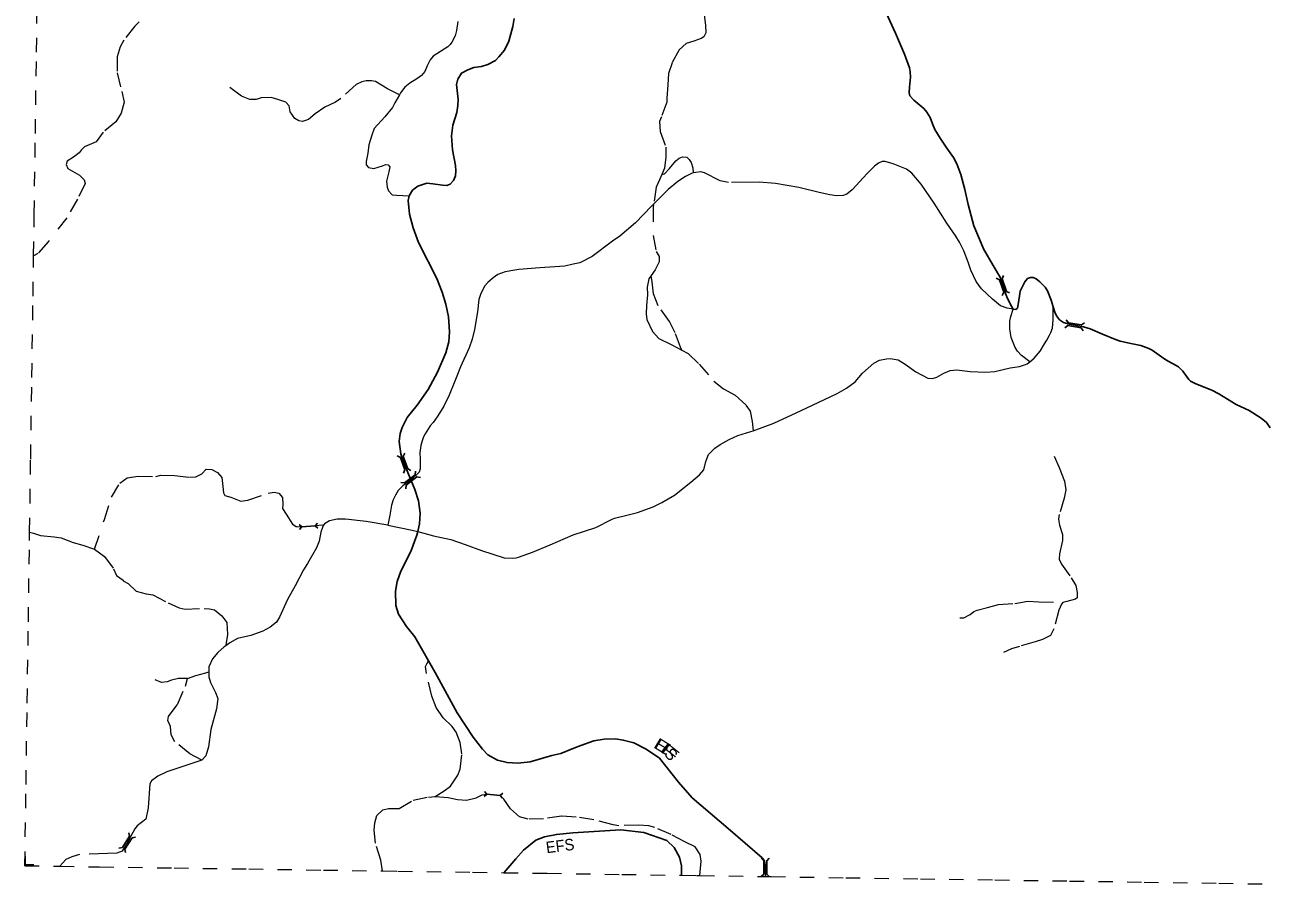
# Model space of a CAD drawing. Extents: x 703.1 to 728.9, y 7316.2 to 7344.3.
# Drawn here: x 703.06 to 711.69, y 7316.45 to 7322.44 of the extents above; entities that cross this region are included whole.
import ezdxf
from ezdxf.enums import TextEntityAlignment as Align

# ---------------------------------------------------------------- set-up
doc = ezdxf.new("R2010")
doc.units = 0
doc.header["$LTSCALE"] = 0.032
for name, pattern in [('DOTTED', [1.5, 0.3, -1.2]), ('LONG_DASHED', [7.5, 6, -1.5]), ('MEDIUM_DASHED', [4.5, 3, -1.5]), ('SHORT_DASHED', [2.7, 1.5, -1.2])]:
    doc.linetypes.add(name, pattern=pattern)
for name, color, linetype, lineweight in [('10', 7, 'Continuous', 25), ('15', 7, 'Continuous', 25), ('31', 7, 'Continuous', 25), ('4', 7, 'LONG_DASHED', 25), ('5', 7, 'LONG_DASHED', 13), ('58', 7, 'SHORT_DASHED', 13), ('6', 7, 'MEDIUM_DASHED', 13), ('63', 7, 'Continuous', 25), ('7', 7, 'DOTTED', 13)]:
    doc.layers.add(name, color=color, linetype=linetype, lineweight=lineweight)
doc.layers.add('61', color=7, linetype='Continuous')

msp = doc.modelspace()

# ---------------------------------------------------------------- linework, layer by layer
at = {"layer": '10'}
for p, q in [((709.8594, 7320.7025), (709.8485, 7320.68)), ((709.8787, 7320.5926), (709.8485, 7320.68)), ((709.8598, 7320.5861), (709.8487, 7320.5637)), ((709.901, 7320.5818), (709.8787, 7320.5926)), ((710.294, 7320.3948), (710.3086, 7320.3746)), ((710.3999, 7320.3595), (710.3086, 7320.3746)), ((710.42, 7320.374), (710.3999, 7320.3595)), ((710.3966, 7320.3397), (710.411, 7320.3194)), ((705.7005, 7319.469), (705.6899, 7319.4464)), ((705.7213, 7319.3594), (705.6899, 7319.4464)), ((705.7025, 7319.3526), (705.6918, 7319.3301)), ((705.7438, 7319.3489), (705.7213, 7319.3594)), ((705.776, 7319.3438), (705.7728, 7319.3191)), ((705.6748, 7319.2658), (705.6996, 7319.2627)), ((705.7728, 7319.3191), (705.6996, 7319.2627)), ((705.785, 7319.3033), (705.8097, 7319.2999)), ((703.7854, 7316.8316), (703.7906, 7316.8074)), ((703.7906, 7316.8074), (703.7402, 7316.7299)), ((703.8074, 7316.7965), (703.8318, 7316.8015)), ((703.7158, 7316.7246), (703.7402, 7316.7299)), ((708.232, 7316.655), (708.2144, 7316.6373)), ((708.2144, 7316.5448), (708.2144, 7316.6373)), ((708.1944, 7316.5448), (708.1767, 7316.5273)), ((708.232, 7316.5273), (708.2144, 7316.5448))]:
    msp.add_line(p, q, dxfattribs=at)
for points in [[(709.8598, 7320.5861), (709.8296, 7320.6735), (709.8071, 7320.6845)], [(710.3966, 7320.3397), (710.3053, 7320.3548), (710.285, 7320.3403)], [(705.7025, 7319.3526), (705.6711, 7319.4396), (705.6485, 7319.4502)], [(705.785, 7319.3033), (705.7118, 7319.2468), (705.7086, 7319.222)], [(703.8074, 7316.7965), (703.7569, 7316.7189), (703.7621, 7316.6945)], [(708.1944, 7316.5448), (708.1944, 7316.6373), (708.1767, 7316.655)]]:
    msp.add_lwpolyline(points, dxfattribs=at)
at = {"layer": '15'}
for points in [[(706.4601, 7322.4886), (706.4525, 7322.4332), (706.4236, 7322.3299), (706.3933, 7322.2682), (706.3537, 7322.2223), (706.331, 7322.1958), (706.2769, 7322.1694), (706.2328, 7322.1555), (706.1812, 7322.148), (706.1384, 7322.1316), (706.0956, 7322.1089), (706.0704, 7322.0661), (706.0604, 7322.0296), (706.073, 7321.925), (706.0698, 7321.8841), (706.0622, 7321.8363), (706.0346, 7321.7481), (706.0257, 7321.6725), (706.0314, 7321.5749), (706.0528, 7321.4679), (706.0566, 7321.4301), (706.0541, 7321.3948), (706.039, 7321.3621), (706.0163, 7321.3369), (705.9924, 7321.3293), (705.9622, 7321.3306), (705.8955, 7321.3407), (705.8533, 7321.3438), (705.7916, 7321.3236), (705.7551, 7321.2947), (705.7314, 7321.2569)], [(705.7314, 7321.2569), (705.7236, 7321.2241), (705.7349, 7321.1284), (705.7589, 7321.034), (705.7972, 7320.9313), (705.9244, 7320.6832), (705.9602, 7320.5881)], [(705.9602, 7320.5881), (705.9867, 7320.5049), (706.0055, 7320.4168), (706.0106, 7320.3122), (706.0061, 7320.2411), (705.9873, 7320.1655), (705.9281, 7320.0308), (705.8632, 7319.9117), (705.7864, 7319.8034), (705.7172, 7319.7165), (705.6825, 7319.6479), (705.6687, 7319.6063), (705.6624, 7319.5497), (705.6737, 7319.4653), (705.697, 7319.3979), (705.7436, 7319.2842)], [(705.7436, 7319.2842), (705.7713, 7319.2165), (705.7959, 7319.1366), (705.8085, 7319.0522), (705.8035, 7318.9791), (705.7913, 7318.9244)], [(705.7913, 7318.9244), (705.7858, 7318.8998), (705.7424, 7318.7858), (705.6744, 7318.6497), (705.6493, 7318.578), (705.6373, 7318.5093), (705.6385, 7318.4098), (705.6587, 7318.3506), (705.7128, 7318.2637), (705.7714, 7318.1938), (705.8268, 7318.0956), (705.8658, 7318.0262), (705.9111, 7317.9457)], [(705.9111, 7317.9457), (706.064, 7317.6643), (706.1755, 7317.4949), (706.2409, 7317.4117), (706.2774, 7317.3727), (706.3442, 7317.3362), (706.4121, 7317.3198), (706.4864, 7317.316), (706.572, 7317.3248), (706.7212, 7317.3696), (706.7842, 7317.3822), (706.8761, 7317.4199), (706.9239, 7317.4376), (707.0146, 7317.4703), (707.0863, 7317.4829), (707.165, 7317.4836), (707.2179, 7317.476), (707.2922, 7317.4571), (707.3765, 7317.4118), (707.4697, 7317.3513), (707.6006, 7317.1826), (707.6957, 7317.0749), (707.9475, 7316.8608), (708.1822, 7316.6586), (708.198, 7316.6379), (708.2043, 7316.6102), (708.2052, 7316.5481), (708.2055, 7316.5281)], [(706.388, 7316.5546), (706.4717, 7316.6498), (706.5265, 7316.7112), (706.6104, 7316.7805), (706.6717, 7316.8048), (706.7539, 7316.8209), (706.8685, 7316.8322), (707.2007, 7316.8532), (707.362, 7316.8338), (707.5201, 7316.7773), (707.5717, 7316.7289), (707.6088, 7316.6627), (707.6217, 7316.603), (707.6217, 7316.5366)]]:
    msp.add_lwpolyline(points, dxfattribs=at)
at = {"layer": '31'}
for p, q in [((704.967, 7318.9734), (704.9858, 7318.957)), ((704.9858, 7318.957), (704.9694, 7318.9382)), ((705.0781, 7318.9632), (704.9858, 7318.957)), ((705.0944, 7318.9819), (705.0781, 7318.9632)), ((705.0781, 7318.9632), (705.0968, 7318.9467)), ((706.2718, 7317.0995), (706.2525, 7317.0836)), ((706.2558, 7317.1187), (706.2718, 7317.0995)), ((706.3639, 7317.0907), (706.2718, 7317.0995)), ((706.383, 7317.1065), (706.3639, 7317.0907)), ((706.3639, 7317.0907), (706.3796, 7317.0714))]:
    msp.add_line(p, q, dxfattribs=at)
at = {"layer": '4'}
for points in [[(709.0442, 7322.5275), (709.1086, 7322.386), (709.1711, 7322.2413), (709.2064, 7322.1454), (709.2114, 7322.1169), (709.2133, 7322.0807), (709.2061, 7322.011), (709.2029, 7321.9716), (709.2086, 7321.95), (709.2362, 7321.9202), (709.3047, 7321.8631), (709.3257, 7321.8377), (709.3491, 7321.8003), (709.3663, 7321.7559), (709.3805, 7321.7178), (709.4186, 7321.6569), (709.4655, 7321.5871), (709.5109, 7321.5223), (709.5337, 7321.4792), (709.5619, 7321.4036), (709.5905, 7321.3008), (709.613, 7321.1968), (709.6424, 7321.0832), (709.6526, 7321.0476), (709.6922, 7320.955), (709.7201, 7320.889), (709.7871, 7320.7723), (709.8375, 7320.6867), (709.847, 7320.6619), (709.8628, 7320.601), (709.8866, 7320.5433), (709.9158, 7320.4856), (709.9266, 7320.4691)], [(709.9266, 7320.4691), (709.945, 7320.4672), (709.9564, 7320.4767), (709.9608, 7320.5021), (709.9685, 7320.5623), (709.9742, 7320.5953), (710.0071, 7320.6588), (710.0243, 7320.6823), (710.0452, 7320.6899), (710.0649, 7320.6899), (710.0858, 7320.6797), (710.1112, 7320.6601), (710.1476, 7320.6213), (710.1647, 7320.596), (710.1888, 7320.5325), (710.2038, 7320.4856)], [(710.2038, 7320.4856), (710.2152, 7320.4494), (710.2272, 7320.4221), (710.2475, 7320.3961)], [(710.2475, 7320.3961), (710.2754, 7320.3771), (710.316, 7320.3638), (710.414, 7320.3466), (710.4597, 7320.3333), (710.5453, 7320.2959), (710.637, 7320.259)], [(710.637, 7320.259), (710.6687, 7320.247), (710.7436, 7320.2305), (710.8121, 7320.2172), (710.8669, 7320.1968), (710.891, 7320.1848), (710.9563, 7320.1378), (710.9862, 7320.1169), (711.0731, 7320.0687), (711.1032, 7320.0395), (711.145, 7319.9811), (711.1571, 7319.9684), (711.1945, 7319.9494), (711.3042, 7319.9056), (711.3534, 7319.8802), (711.4746, 7319.8059), (711.5634, 7319.7647), (711.6474, 7319.7114), (711.6835, 7319.6815), (711.7089, 7319.6454)]]:
    msp.add_lwpolyline(points, dxfattribs=at)
at = {"layer": '5'}
for points in [[(706.0685, 7322.4684), (706.0604, 7322.4044), (706.0508, 7322.3676), (706.0288, 7322.3242), (706.017, 7322.308), (706.0012, 7322.2911), (705.8983, 7322.2257), (705.8784, 7322.2006), (705.8571, 7322.1587), (705.8398, 7322.1198), (705.8178, 7322.0925), (705.7847, 7322.0683), (705.7369, 7322.0388), (705.7023, 7322.0109), (705.6722, 7321.9726), (705.6641, 7321.9587)], [(705.6641, 7321.9587), (705.6314, 7321.9028), (705.616, 7321.8697), (705.563, 7321.8057), (705.4884, 7321.724), (705.4715, 7321.6784), (705.4509, 7321.6107), (705.4447, 7321.5534), (705.4322, 7321.4945), (705.4322, 7321.4725), (705.4483, 7321.4526), (705.4873, 7321.446), (705.5468, 7321.4658), (705.5682, 7321.4747), (705.5866, 7321.471), (705.5968, 7321.4577), (705.5914, 7321.4224), (705.5737, 7321.3584), (705.5796, 7321.3158), (705.5884, 7321.2922), (705.6141, 7321.2635), (705.6443, 7321.2606), (705.7314, 7321.2569)], [(709.9266, 7320.4691), (709.8848, 7320.4758), (709.8379, 7320.4934), (709.7816, 7320.5394), (709.7053, 7320.6104), (709.6676, 7320.6608), (709.6307, 7320.7401), (709.6121, 7320.7945), (709.583, 7320.8733), (709.5522, 7320.9339), (709.5285, 7320.976), (709.4639, 7321.0671), (709.3761, 7321.2065), (709.2858, 7321.3363), (709.2224, 7321.4146), (709.1838, 7321.4405), (709.0933, 7321.4792), (709.0363, 7321.4948), (709.0162, 7321.4948), (708.9893, 7321.484), (708.9619, 7321.4615), (708.912, 7321.4106), (708.808, 7321.2986), (708.7696, 7321.2687), (708.7451, 7321.2594), (708.6977, 7321.2569), (708.6517, 7321.2623), (708.5786, 7321.2805), (708.4367, 7321.3142), (708.275, 7321.3417), (708.1612, 7321.3514), (707.9482, 7321.348), (707.8921, 7321.3617), (707.783, 7321.4155), (707.7576, 7321.4229), (707.7228, 7321.4195), (707.7029, 7321.4152)], [(707.7029, 7321.4152), (707.691, 7321.4126), (707.6504, 7321.3916), (707.5966, 7321.3548), (707.5296, 7321.3005), (707.429, 7321.1982)], [(707.429, 7321.1982), (707.4146, 7321.1835), (707.3028, 7321.0699), (707.1944, 7320.9773), (707.1426, 7320.9426), (707.0014, 7320.8344), (706.9175, 7320.7903), (706.8705, 7320.781), (706.8123, 7320.7683), (706.6388, 7320.7565), (706.4937, 7320.7453), (706.4658, 7320.7409), (706.398, 7320.7281), (706.3481, 7320.71), (706.3149, 7320.6865), (706.2784, 7320.6552), (706.2559, 7320.6288), (706.2408, 7320.5994), (706.23, 7320.5779), (706.2165, 7320.5353), (706.2053, 7320.4496), (706.186, 7320.3288), (706.1686, 7320.2597), (706.1491, 7320.201), (706.0892, 7320.0678), (706.0664, 7320.015), (706.0498, 7319.9695), (706.0085, 7319.872), (705.9713, 7319.7957), (705.9312, 7319.7291), (705.8975, 7319.6826), (705.8767, 7319.6581), (705.8429, 7319.6028), (705.8317, 7319.5817), (705.8224, 7319.5538), (705.8124, 7319.522), (705.805, 7319.4736), (705.807, 7319.4261), (705.8082, 7319.359), (705.8019, 7319.336), (705.7493, 7319.2885), (705.7436, 7319.2842)], [(710.0405, 7320.1035), (709.9827, 7320.148), (709.9553, 7320.1784), (709.9392, 7320.2028), (709.9111, 7320.2714), (709.9013, 7320.3321), (709.903, 7320.3864), (709.9084, 7320.4192), (709.9266, 7320.4691)], [(710.0405, 7320.1035), (710.0711, 7320.1285), (710.1136, 7320.1779), (710.144, 7320.2284), (710.1599, 7320.2533), (710.1785, 7320.2886), (710.1878, 7320.3081), (710.1986, 7320.3375), (710.2028, 7320.3948), (710.2038, 7320.4856)], [(708.1199, 7319.6242), (708.2648, 7319.6762), (708.4177, 7319.7501), (708.5327, 7319.802), (708.7042, 7319.8822), (708.7671, 7319.9209), (708.8273, 7319.964), (708.8786, 7320.0257), (708.9571, 7320.0937), (708.9975, 7320.1143), (709.0465, 7320.1246), (709.0724, 7320.1275), (709.1262, 7320.1167), (709.1761, 7320.0874), (709.25, 7320.0345), (709.3339, 7319.9904), (709.3662, 7319.9884), (709.3961, 7319.9963), (709.4433, 7320.0241), (709.4707, 7320.0369), (709.4869, 7320.0427), (709.5338, 7320.0467), (709.6265, 7320.0369), (709.7347, 7320.0325), (709.7976, 7320.0364), (709.9037, 7320.0623), (709.9705, 7320.0697), (710.0052, 7320.0814), (710.0238, 7320.0888), (710.0405, 7320.1035)], [(705.7913, 7318.9244), (705.9012, 7318.8939), (706.0199, 7318.869), (706.1209, 7318.8342), (706.234, 7318.7926), (706.3923, 7318.7426), (706.4508, 7318.7397), (706.4738, 7318.7412), (706.4914, 7318.7461), (706.5873, 7318.7818), (706.7104, 7318.8332), (706.8711, 7318.9018), (707.0269, 7318.9527), (707.1367, 7319.0089), (707.1573, 7319.0182), (707.2434, 7319.0373), (707.3165, 7319.0574), (707.4257, 7319.0966), (707.4861, 7319.1254), (707.5732, 7319.1768), (707.687, 7319.2674), (707.7484, 7319.3188), (707.7768, 7319.3521), (707.7924, 7319.4118), (707.8112, 7319.4593), (707.8548, 7319.5044), (707.892, 7319.5283), (707.9539, 7319.5646), (708.0131, 7319.591), (708.1036, 7319.6184), (708.1199, 7319.6242)], [(705.7436, 7319.2842), (705.6866, 7319.2415), (705.6543, 7319.2092), (705.6358, 7319.1779), (705.6214, 7319.1436), (705.6082, 7319.1083), (705.5964, 7319.0374), (705.5844, 7318.9678)], [(705.5844, 7318.9678), (705.4339, 7318.9951), (705.2899, 7319.0096), (705.2318, 7319.0096), (705.1796, 7318.9989), (705.1429, 7318.9777), (705.1371, 7318.968)], [(705.1371, 7318.968), (705.1313, 7318.9583), (705.1178, 7318.9206), (705.1071, 7318.8587), (705.0888, 7318.8103), (705.0255, 7318.703), (704.9974, 7318.6594), (704.9394, 7318.5472), (704.8877, 7318.4534), (704.8316, 7318.3306), (704.8098, 7318.2938), (704.7668, 7318.259), (704.7146, 7318.2329), (704.6325, 7318.2019), (704.5387, 7318.1806), (704.4865, 7318.1506), (704.4582, 7318.1308)], [(705.5844, 7318.9678), (705.7527, 7318.9351), (705.7913, 7318.9244)], [(704.4582, 7318.1308), (704.4478, 7318.1236), (704.4033, 7318.0839), (704.3651, 7318.0403), (704.3409, 7317.9842), (704.3405, 7317.9494)], [(704.3405, 7317.9494), (704.34, 7317.9146), (704.3525, 7317.8759), (704.3868, 7317.8052), (704.4033, 7317.7636), (704.3936, 7317.692), (704.3554, 7317.5489), (704.338, 7317.4289), (704.3201, 7317.367), (704.2911, 7317.3361)], [(704.2911, 7317.3361), (704.1316, 7317.2819), (704.0499, 7317.2549), (703.9861, 7317.2249), (703.9435, 7317.193), (703.931, 7317.1726), (703.9203, 7317.0053), (703.9043, 7316.9269), (703.8434, 7316.8805), (703.826, 7316.8582), (703.768, 7316.7528), (703.7385, 7316.7053), (703.7027, 7316.6899), (703.4436, 7316.6802), (703.3895, 7316.6657), (703.3484, 7316.6453), (703.3054, 7316.5992)]]:
    msp.add_lwpolyline(points, dxfattribs=at)
at = {"layer": '58'}
msp.add_line((703.0632, 7316.6027), (703.3054, 7316.5992), dxfattribs=at)
for points in [[(703.1239, 7320.8393), (703.128, 7321.1237), (703.1361, 7321.6888), (703.1442, 7322.254), (703.1522, 7322.8191), (703.1603, 7323.3842), (703.1684, 7323.9493), (703.1684, 7323.9498)], [(703.0964, 7318.9203), (703.1037, 7319.4283), (703.1118, 7319.9935), (703.1199, 7320.5586), (703.1239, 7320.8393)], [(703.0632, 7316.6027), (703.0713, 7317.1678), (703.0794, 7317.733), (703.0875, 7318.2981), (703.0956, 7318.8632), (703.0964, 7318.9203)], [(703.3054, 7316.5992), (703.5813, 7316.5953), (704.0995, 7316.5878), (704.6177, 7316.5803), (705.1358, 7316.5728), (705.547, 7316.5668)], [(705.547, 7316.5668), (705.654, 7316.5653), (706.1722, 7316.5578), (706.388, 7316.5546)], [(706.388, 7316.5546), (706.6903, 7316.5502), (707.2085, 7316.5427), (707.6217, 7316.5366)], [(707.6217, 7316.5366), (707.7267, 7316.5351), (707.7507, 7316.5347), (708.2055, 7316.5281)], [(708.2055, 7316.5281), (708.2448, 7316.5275), (708.763, 7316.5198), (709.2812, 7316.5122), (709.7993, 7316.5045), (710.3175, 7316.4968), (710.8357, 7316.4891), (711.3539, 7316.4814), (711.872, 7316.4736), (712.3902, 7316.4659), (712.9084, 7316.4581), (713.1751, 7316.4541)]]:
    msp.add_lwpolyline(points, dxfattribs=at)
at = {"layer": '6'}
for p, q in [((704.9858, 7318.957), (705.0781, 7318.9632)), ((706.3639, 7317.0907), (706.2718, 7317.0995))]:
    msp.add_line(p, q, dxfattribs=at)
for points in [[(703.8579, 7322.4651), (703.8261, 7322.4359), (703.7502, 7322.3369), (703.7258, 7322.2908), (703.7041, 7322.2216), (703.7041, 7322.1104), (703.7359, 7321.9809), (703.7535, 7321.9076), (703.7318, 7321.8316), (703.6952, 7321.7706), (703.6078, 7321.6994), (703.5576, 7321.6316), (703.4777, 7321.5963), (703.4533, 7321.5746), (703.4411, 7321.5542), (703.4017, 7321.5258), (703.357, 7321.4973), (703.3509, 7321.4749), (703.3618, 7321.4464), (703.4431, 7321.4003), (703.4757, 7321.3678), (703.4825, 7321.342), (703.4282, 7321.2321), (703.3544, 7321.1039), (703.2242, 7320.9357), (703.1544, 7320.8563), (703.1239, 7320.8393)], [(707.7803, 7322.5128), (707.7888, 7322.4411), (707.7915, 7322.3878), (707.7771, 7322.3617), (707.76, 7322.3482), (707.7077, 7322.3301), (707.6545, 7322.3139), (707.6067, 7322.2697), (707.5575, 7322.1808), (707.5332, 7322.1069), (707.5286, 7322.0284), (707.5219, 7321.9341), (707.5201, 7321.908), (707.4831, 7321.806), (707.4701, 7321.7722), (707.4755, 7321.7027), (707.5134, 7321.5944), (707.5138, 7321.5245), (707.5039, 7321.4478), (707.4854, 7321.4039)], [(707.4854, 7321.4039), (707.4705, 7321.3684), (707.4458, 7321.3174), (707.429, 7321.1982)], [(707.429, 7321.1982), (707.4259, 7321.1758), (707.4264, 7320.9805), (707.4467, 7320.8691), (707.4666, 7320.8348), (707.4666, 7320.7978), (707.4386, 7320.7419), (707.4119, 7320.7028)], [(707.4119, 7320.7028), (707.3958, 7320.6792), (707.3841, 7320.6215), (707.3868, 7320.5682), (707.3805, 7320.4952), (707.3773, 7320.4361), (707.3809, 7320.3964), (707.4215, 7320.3143), (707.4648, 7320.2656), (707.5554, 7320.2209), (707.624, 7320.1849)], [(707.624, 7320.1849), (707.669, 7320.1614), (707.7443, 7320.0879), (707.8462, 7319.9697), (707.9147, 7319.9165), (707.995, 7319.8723), (708.0702, 7319.8033), (708.0991, 7319.76), (708.1126, 7319.6896), (708.1199, 7319.6242)], [(710.2102, 7319.4484), (710.2455, 7319.3688), (710.2818, 7319.274), (710.2918, 7319.2135), (710.2797, 7319.157), (710.2455, 7319.0431), (710.2399, 7319.0103), (710.247, 7318.969), (710.2681, 7318.9034), (710.2691, 7318.8621), (710.248, 7318.7693), (710.2454, 7318.7335), (710.2616, 7318.6982), (710.3291, 7318.6024), (710.3603, 7318.549), (710.3704, 7318.5006), (710.3689, 7318.4648), (710.3579, 7318.4547), (710.2984, 7318.4386), (710.2702, 7318.4325)], [(703.5466, 7318.8028), (703.6159, 7319.0092), (703.6659, 7319.1634), (703.7235, 7319.2613), (703.773, 7319.2975), (703.8495, 7319.3092), (703.973, 7319.3076), (704.007, 7319.3156), (704.1028, 7319.3131), (704.2053, 7319.3013), (704.2499, 7319.3038), (704.291, 7319.3257), (704.3221, 7319.3568), (704.362, 7319.3547), (704.3998, 7319.3354), (704.4301, 7319.2992), (704.4385, 7319.2379), (704.4418, 7319.1933), (704.4528, 7319.174), (704.4931, 7319.1631), (704.5628, 7319.1362), (704.6107, 7319.1429), (704.7523, 7319.1904), (704.7934, 7319.1971), (704.8262, 7319.1912), (704.8531, 7319.1618), (704.8539, 7319.1114), (704.8514, 7319.0836), (704.8775, 7319.045), (704.9212, 7318.9752), (704.946, 7318.9605), (704.9529, 7318.9597), (704.9858, 7318.957)], [(703.0964, 7318.9203), (703.1239, 7318.9138), (703.1718, 7318.8961), (703.2668, 7318.8869), (703.3147, 7318.8802), (703.3995, 7318.8474), (703.4668, 7318.8297), (703.5466, 7318.8028)], [(705.1371, 7318.968), (705.1315, 7318.9676), (705.0781, 7318.9632)], [(703.5466, 7318.8028), (703.6166, 7318.7513), (703.6792, 7318.6652), (703.6988, 7318.6194), (703.7456, 7318.5858), (703.7456, 7318.5829), (703.7811, 7318.5642), (703.8353, 7318.5109), (703.9054, 7318.4922), (703.9512, 7318.4848), (704.0578, 7318.4296), (704.1353, 7318.395), (704.176, 7318.3861), (704.3078, 7318.3907), (704.3452, 7318.3879), (704.3798, 7318.3795), (704.4302, 7318.3384), (704.4658, 7318.2935), (704.4704, 7318.2103), (704.4613, 7318.1509), (704.4582, 7318.1308)], [(710.2702, 7318.4325), (710.2601, 7318.4204), (710.243, 7318.3771), (710.2087, 7318.249), (710.184, 7318.2031), (710.1295, 7318.1739), (710.0771, 7318.1577), (709.9683, 7318.1265), (709.9128, 7318.1103), (709.8584, 7318.0841)], [(705.9114, 7317.0828), (705.9746, 7317.1225), (706.0191, 7317.1559), (706.0692, 7317.231), (706.0859, 7317.2741), (706.0984, 7317.3812), (706.0866, 7317.4583), (706.0588, 7317.5307), (706.031, 7317.5696), (705.967, 7317.6294), (705.9198, 7317.7017), (705.8892, 7317.781), (705.851, 7317.9375), (705.8454, 7317.9876), (705.8552, 7318.0062), (705.8658, 7318.0262)], [(704.1934, 7317.9041), (704.1309, 7317.9041), (704.0825, 7317.8928), (704.0513, 7317.8814), (704.0129, 7317.8757), (703.9674, 7317.8942)], [(704.2911, 7317.3361), (704.2091, 7317.3792), (704.1053, 7317.4631), (704.0783, 7317.5129), (704.074, 7317.5698), (704.0569, 7317.6125), (704.0612, 7317.6395), (704.1223, 7317.7235), (704.1792, 7317.8501), (704.1934, 7317.9041)], [(704.1934, 7317.9041), (704.2503, 7317.9241), (704.3204, 7317.9438), (704.3405, 7317.9494)], [(705.9114, 7317.0828), (706.0024, 7317.0766), (706.0678, 7317.0627), (706.1303, 7317.0585), (706.1971, 7317.0738), (706.2374, 7317.0947), (706.2718, 7317.0995)], [(707.7507, 7316.5347), (707.7588, 7316.6336), (707.7533, 7316.6809), (707.7185, 7316.7337), (707.6448, 7316.7685), (707.551, 7316.8193), (707.4384, 7316.868), (707.3953, 7316.8791), (707.3244, 7316.8847), (707.1868, 7316.8805), (707.1478, 7316.886), (707.013, 7316.9222), (706.8921, 7316.9403), (706.7899, 7316.948), (706.6648, 7316.9285), (706.5577, 7316.9271), (706.498, 7316.9424), (706.4361, 7316.9973), (706.3885, 7317.066), (706.3639, 7317.0907)], [(705.547, 7316.5668), (705.5347, 7316.6419), (705.4986, 7316.7602), (705.4888, 7316.8492), (705.493, 7316.902), (705.5083, 7316.9521), (705.5486, 7316.991), (705.5875, 7317.0008), (705.6612, 7316.9994), (705.7599, 7317.0578), (705.8669, 7317.08), (705.9114, 7317.0828)]]:
    msp.add_lwpolyline(points, dxfattribs=at)
at = {"layer": '63'}
msp.add_lwpolyline([(703.0648, 7316.6704), (703.0648, 7316.6088), (703.1255, 7316.6088)], dxfattribs=at)
at = {"layer": '7'}
for points in [[(705.6641, 7321.9587), (705.618, 7321.981), (705.5802, 7321.9985), (705.5386, 7322.0262), (705.4971, 7322.0502), (705.4694, 7322.0557), (705.4335, 7322.0557), (705.4021, 7322.0474), (705.3643, 7322.0299), (705.2563, 7321.9321), (705.2203, 7321.908), (705.1465, 7321.872), (705.0792, 7321.825), (705.0326, 7321.7866), (704.9911, 7321.7728), (704.9653, 7321.7783), (704.9376, 7321.7931), (704.9053, 7321.8393), (704.8979, 7321.8808), (704.8743, 7321.9061), (704.8199, 7321.9246), (704.7728, 7321.9394), (704.7046, 7321.9366), (704.6695, 7321.9264), (704.6252, 7321.9264), (704.5671, 7321.9495), (704.4467, 7322.0386)], [(707.4854, 7321.4039), (707.5044, 7321.4085), (707.5384, 7321.4469), (707.5827, 7321.4994), (707.6071, 7321.5171), (707.6292, 7321.5267), (707.6588, 7321.5245), (707.675, 7321.5097), (707.689, 7321.4883), (707.7009, 7321.4513), (707.7029, 7321.4152)], [(707.624, 7320.1849), (707.6165, 7320.205), (707.5785, 7320.3058), (707.5403, 7320.3845), (707.4605, 7320.4921), (707.4281, 7320.5754), (707.4189, 7320.6599), (707.4119, 7320.7028)], [(709.5549, 7318.3259), (709.5823, 7318.3259), (709.6269, 7318.3476), (709.6521, 7318.3682), (709.6761, 7318.3785), (709.747, 7318.3979), (709.8235, 7318.4185), (709.9378, 7318.4242), (710.0282, 7318.4414), (710.1047, 7318.4357), (710.2702, 7318.4325)]]:
    msp.add_lwpolyline(points, dxfattribs=at)

# ---------------------------------------------------------------- texts
at = {"layer": '61'}
for s, rotation, width, p in [('E', 328.599, 1.6, (707.4684, 7317.3991)), ('F', 321.97, 2, (707.5159, 7317.3632)), ('EFS', 7.228, 0.95, (706.7846, 7316.7017))]:
    msp.add_text(s, height=0.08, rotation=rotation, dxfattribs=dict(at, width=width)).set_placement(p, align=Align.CENTER)
msp.add_text('S', height=0.08, rotation=311.701, dxfattribs=at).set_placement((707.5206, 7317.3506), align=Align.CENTER)

doc.saveas('drawing.dxf')
